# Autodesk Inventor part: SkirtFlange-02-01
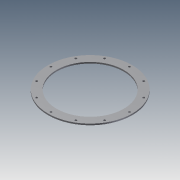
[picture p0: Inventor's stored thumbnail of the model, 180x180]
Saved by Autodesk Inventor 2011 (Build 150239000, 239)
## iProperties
Created: 2010-06
Part Number: SkirtFlange-02-01
Document SubType Name: Modeling
Designer: mklassen
Density: 1 g/cm^3
OD: 24.000 in
THK: 0.500 in
WDT: 3.000 in
BHN: 12.000 ul
BHD: 0.750 in
BCD: 14.000 in
Author: mklassen
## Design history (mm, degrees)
sketch "skSkirtFlange"
  geometry: C1 r 304.8 at (0, 0); C2 r 381 at (0, 0); 1 further point
  constraints: 2 centre point, 2 coincident
  dimensions: "d0" = 76.2 radial gap between concentric circles of C2 C1 (derived); "d1" = 609.6 diameter of C1 (derived)
extrude "SkirtFlange" new body sketch "skSkirtFlange" stored distance "d2" = 12.7 (derived); taper "d3" = 0 deg
sketch "skBoltHole"
  geometry: C1 r 304.8 at (0, 0) reference; 2 further points
  constraints: 1 coincident, 1 vertical alignment
  dimensions: "d7" = 355.6 distance of point (0, 355.6) point (0, 0) (= BCD)
hole "BoltHole" sketch "skBoltHole" at (0, 355.6) diameter "d8" = 19.05 (derived); stored, may be unused: countersink angle "d12" = 82 deg, drill point angle "d14" = 118 deg; dims "d9" = 19.05, "d10" = 9.525, "d11" = 6.35, "d13" = 25.4
pattern_circular "BoltCircle" dims angle "d16" = 360 deg
body "Solid1"
other parameters: "BCD" = 355.6 [user parameter; used in 2 equation terms], "d4" = 0, "d5" = 0, "d6" = 0
